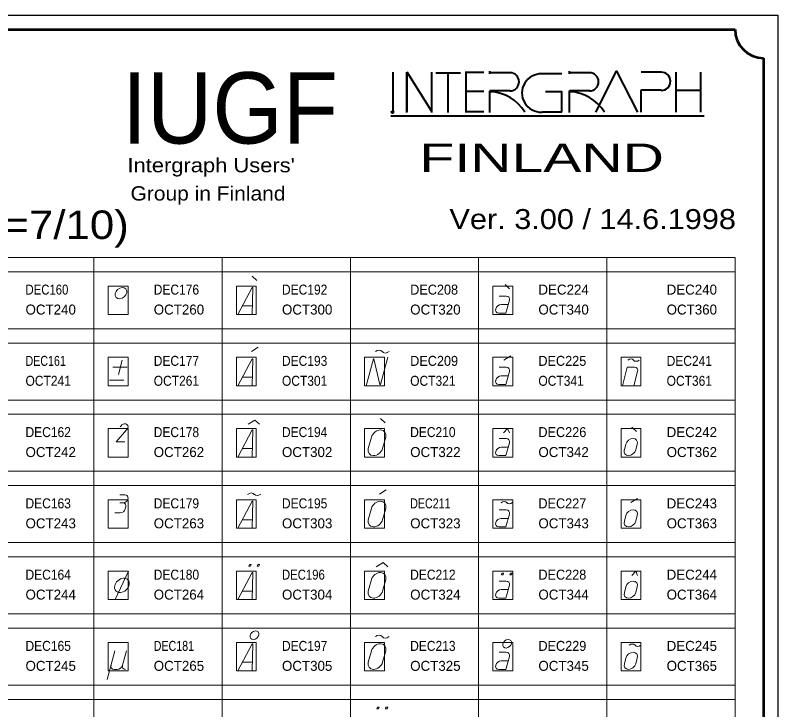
# Model space of a CAD drawing. Extents: x -200 to 7300, y -200 to 4800.
# Drawn here: x 4624 to 7300, y 2364 to 4800 of the extents above; entities that cross this region are included whole.
import ezdxf
from ezdxf.enums import TextEntityAlignment as Align

# ---------------------------------------------------------------- set-up
doc = ezdxf.new("R2010")
doc.units = 0
doc.header["$LTSCALE"] = 14
doc.header["$PDMODE"] = 32
doc.header["$PDSIZE"] = 7
for name, color, linetype, lineweight in [('1', 7, 'Continuous', 13), ('5', 7, 'Continuous', 40), ('6', 7, 'Continuous', 13), ('63', 7, 'Continuous', 13)]:
    doc.layers.add(name, color=color, linetype=linetype, lineweight=lineweight)
doc.layers.add('10', color=7, linetype='Continuous')
doc.layers.add('11', color=7, linetype='Continuous')

msp = doc.modelspace()

# ---------------------------------------------------------------- linework, layer by layer
at = {"layer": '1'}
for p, q in [((5472, 3870), (5456, 3885)), ((6359, 3840), (6343, 3855)), ((6322, 3815), (6347, 3815)), ((5421, 3780), (5457, 3780)), ((6329, 3785), (6354, 3785)), ((5453, 3620), (5477, 3635)), ((4986, 3540), (4999, 3590)), ((6339, 3590), (6363, 3605)), ((4967, 3565), (5017, 3565)), ((6322, 3565), (6347, 3565)), ((6329, 3535), (6354, 3535)), ((6808, 3550), (6795, 3500)), ((4955, 3520), (5005, 3520)), ((5421, 3530), (5457, 3530)), ((5922, 3370), (5906, 3385)), ((6804, 3340), (6788, 3355)), ((5874, 3320), (5863, 3280)), ((5924, 3320), (5913, 3280)), ((6322, 3315), (6347, 3315)), ((6767, 3295), (6762, 3275)), ((6807, 3295), (6802, 3275)), ((5421, 3280), (5457, 3280)), ((6329, 3285), (6354, 3285)), ((5902, 3120), (5926, 3135)), ((5009, 3117), (4991, 3117)), ((6784, 3090), (6808, 3105)), ((5002, 3089), (4991, 3089)), ((4992, 3054), (4974, 3054)), ((5012, 3075), (5010, 3068)), ((5874, 3070), (5863, 3030)), ((5924, 3070), (5913, 3030)), ((6322, 3065), (6347, 3065)), ((5421, 3030), (5457, 3030)), ((6329, 3035), (6354, 3035)), ((6767, 3045), (6762, 3025)), ((6807, 3045), (6802, 3025)), ((4975, 2750), (5022, 2850)), ((5874, 2820), (5863, 2780)), ((5924, 2820), (5913, 2780)), ((6322, 2815), (6347, 2815)), ((6329, 2785), (6354, 2785)), ((6767, 2795), (6762, 2775)), ((6807, 2795), (6802, 2775)), ((5421, 2780), (5457, 2780)), ((4974, 2570), (4947, 2470)), ((5014, 2570), (5000, 2520)), ((5874, 2570), (5863, 2530)), ((5924, 2570), (5913, 2530)), ((6322, 2565), (6347, 2565)), ((6767, 2545), (6762, 2525)), ((6807, 2545), (6802, 2525)), ((5421, 2530), (5457, 2530)), ((6329, 2535), (6354, 2535)), ((4971, 2505), (4981, 2505))]:
    msp.add_line(p, q, dxfattribs=at)
for points in [[(5405, 3750), (5455, 3845), (5458, 3845), (5456, 3750)], [(6358, 3800), (6346, 3755), (6321, 3755)], [(5405, 3500), (5455, 3595), (5458, 3595), (5456, 3500)], [(5855, 3500), (5881, 3595), (5883, 3595), (5904, 3505), (5906, 3505), (5932, 3600)], [(6755, 3500), (6772, 3565), (6797, 3565)], [(6358, 3550), (6346, 3505), (6321, 3505)], [(5481, 3365), (5465, 3380), (5441, 3365)], [(6358, 3335), (6352, 3350), (6338, 3335)], [(5009, 3304), (4978, 3304), (5015, 3345)], [(5405, 3250), (5455, 3345), (5458, 3345), (5456, 3250)], [(6358, 3300), (6346, 3255), (6321, 3255)], [(5405, 3000), (5455, 3095), (5458, 3095), (5456, 3000)], [(6358, 3050), (6346, 3005), (6321, 3005)], [(5931, 2865), (5915, 2880), (5891, 2865)], [(5405, 2750), (5455, 2845), (5458, 2845), (5456, 2750)], [(6808, 2835), (6802, 2850), (6788, 2835)], [(6358, 2800), (6346, 2755), (6321, 2755)], [(5405, 2500), (5455, 2595), (5458, 2595), (5456, 2500)], [(6358, 2550), (6346, 2505), (6321, 2505)]]:
    msp.add_lwpolyline(points, dxfattribs=at)
for points in [[(5444, 2867), (5450, 2867), (5452, 2873), (5446, 2873)], [(5473, 2867), (5479, 2867), (5481, 2873), (5475, 2873)], [(6330, 2837), (6336, 2837), (6338, 2843), (6332, 2843)], [(6360, 2837), (6366, 2837), (6368, 2843), (6362, 2843)], [(5893, 2367), (5899, 2367), (5901, 2373), (5895, 2373)], [(5923, 2367), (5929, 2367), (5931, 2373), (5925, 2373)]]:
    msp.add_lwpolyline(points, close=True, dxfattribs=at)
for centre, major_axis, ratio in [((4994.91, 3825), (-17.2, -15.05), 0.765566), ((4998.31, 2799.84), (-21.56, -18.83), 0.762607), ((5463.39, 2625), (-12.9, -11.29), 0.765566), ((6350.36, 2595), (-12.9, -11.29), 0.765566)]:
    msp.add_ellipse(centre, major_axis=major_axis, ratio=ratio, dxfattribs=at)
for centre, major_axis, start_param, end_param in [((6343, 3800), (-12.9, -11.29), 2.2896327, 3.860429), ((6325.19, 3770), (-12.9, -11.29), 3.860429, 7.0020216), ((5896.78, 3608), (-14.6, -12.77), 3.0750308, 4.6457939), ((5927.21, 3632), (-14.6, -12.77), 6.2166235, 7.7873867), ((6781.29, 3580), (-12.16, -10.64), 3.0750308, 4.6458271), ((6806.65, 3600), (-12.16, -10.64), 6.2166235, 7.7874198), ((6343, 3550), (-12.9, -11.29), 2.2896327, 3.860429), ((6793, 3550), (-12.9, -11.29), 2.2896327, 3.860429), ((6325.21, 3520), (-12.9, -11.29), 3.860429, 7.0020216), ((5005.28, 3352.61), (-12.04, -10.54), 1.7153279, 5.1862467), ((5899, 3320), (-21.5, -18.81), 2.2896326, 5.4312252), ((6343, 3300), (-12.9, -11.29), 2.2896327, 3.860429), ((6786.93, 3295), (-17.2, -15.05), 2.2896326, 5.4312252), ((5888, 3280), (21.5, 18.81), 2.2896328, 5.4312254), ((6325.22, 3270), (-12.9, -11.29), 3.860429, 7.0020216), ((6781.57, 3275), (17.2, 15.05), 2.2896328, 5.4312254), ((5005.47, 3102.98), (-12.06, -10.55), 0.646299, 3.8615683), ((5447.8, 3107), (-14.6, -12.77), 3.0750308, 4.6457939), ((5477.23, 3132), (-14.6, -12.77), 6.2166235, 7.7873867), ((4997.96, 3075), (-12.04, -10.54), 2.2896326, 3.8604289), ((5899, 3070), (-21.5, -18.81), 2.2896326, 5.4312252), ((6336.31, 3080), (-12.16, -10.64), 3.0750308, 4.6458271), ((6361.67, 3100), (-12.16, -10.64), 6.2166235, 7.7874198), ((4996.08, 3068), (12.04, 10.54), 3.860429, 5.4312252), ((6343, 3050), (-12.9, -11.29), 2.2896327, 3.860429), ((6786.94, 3045), (-17.2, -15.05), 2.2896326, 5.4312252), ((5888, 3030), (21.5, 18.81), 2.2896328, 5.4312254), ((6325.24, 3020), (-12.9, -11.29), 3.860429, 7.0020216), ((6781.58, 3025), (17.2, 15.05), 2.2896328, 5.4312254), ((5899, 2820), (-21.5, -18.81), 2.2896326, 5.4312252), ((6343, 2800), (-12.9, -11.29), 2.2896327, 3.860429), ((6786.96, 2795), (-17.2, -15.05), 2.2896326, 5.4312252), ((6325.25, 2770), (-12.9, -11.29), 3.860429, 7.0020216), ((5888, 2780), (21.5, 18.81), 2.2896328, 5.4312254), ((6781.6, 2775), (17.2, 15.05), 2.2896328, 5.4312254), ((5896.84, 2608), (-14.6, -12.77), 3.0750308, 4.6457939), ((5927.27, 2632), (-14.6, -12.77), 6.2166235, 7.7873867), ((5899, 2570), (-21.5, -18.81), 2.2896326, 5.4312252), ((6786.35, 2580), (-12.16, -10.64), 3.0750308, 4.6458271), ((6811.71, 2600), (-12.16, -10.64), 6.2166235, 7.7874198), ((6343, 2550), (-12.9, -11.29), 2.2896327, 3.860429), ((6786.97, 2545), (-17.2, -15.05), 2.2896326, 5.4312252), ((4975.25, 2520), (12.9, 11.29), 2.2896327, 3.860429), ((4985.25, 2520), (-12.9, -11.29), 0.7188363, 2.2896326), ((5015.25, 2520), (12.9, 11.29), 2.2896328, 3.860429), ((5888, 2530), (21.5, 18.81), 2.2896328, 5.4312254), ((6325.27, 2520), (-12.9, -11.29), 3.860429, 7.0020216), ((6781.61, 2525), (17.2, 15.05), 2.2896328, 5.4312254)]:
    msp.add_ellipse(centre, major_axis=major_axis, ratio=0.765566, start_param=start_param, end_param=end_param, dxfattribs=at)
at = {"layer": '5', "lineweight": 53}
for p, q in [((-50, 4750), (7150, 4750)), ((7250, 4650), (7250, -50))]:
    msp.add_line(p, q, dxfattribs=at)
at = {"layer": '5'}
for p, q in [((6290, 4595), (6290, 4604)), ((6569, 4595), (6569, 4604)), ((5950, 4459), (5950, 4600)), ((5998, 4459), (5998, 4600)), ((5999, 4462), (5999, 4600)), ((6086, 4462), (5999, 4600)), ((6086, 4459), (6086, 4600)), ((6100, 4598), (6187, 4598)), ((6143, 4459), (6143, 4600)), ((6203, 4600), (6269, 4600)), ((6205, 4600), (6205, 4460)), ((6361, 4598), (6290, 4598)), ((6542, 4595), (6473, 4595)), ((6640, 4598), (6569, 4598)), ((6892, 4600), (6821, 4600)), ((6943, 4460), (6943, 4600)), ((7030, 4460), (7030, 4600)), ((6203, 4534), (6269, 4534)), ((6361, 4535), (6290, 4535)), ((6290, 4459), (6290, 4535)), ((6640, 4535), (6569, 4535)), ((6569, 4459), (6569, 4535)), ((6821, 4460), (6821, 4538)), ((6892, 4537), (6821, 4537)), ((6944, 4537), (7027, 4537)), ((5942, 4447), (7042, 4447)), ((6203, 4462), (6269, 4462)), ((6542, 4460), (6473, 4460))]:
    msp.add_line(p, q, dxfattribs=at)
at = {"layer": '5', "lineweight": 25}
msp.add_lwpolyline([(-200, -200), (-200, 4800), (7300, 4800), (7300, -200)], close=True, dxfattribs=at)
at = {"layer": '5'}
for points in [[(6662, 4460), (6734, 4604), (6808, 4460)], [(6662, 4460), (6734, 4604), (6808, 4460)], [(6542, 4460), (6542, 4531), (6485, 4531)]]:
    msp.add_lwpolyline(points, dxfattribs=at)
at = {"layer": '5', "lineweight": 53}
msp.add_arc((7250.23, 4750.23), 100.23, 180.13245, 269.86755, dxfattribs=at)
at = {"layer": '5'}
for centre, radius, start, end in [((6359.95, 4566.47), 32.08, 270, 89.99999), ((6469.54, 4527.31), 67.13, 87.55561, 272.44438), ((6639.2, 4566.47), 32.08, 270, 89.99999), ((6891.34, 4568.25), 32.08, 270, 89.99999), ((6282.86, 4378.09), 153.83, 32.38854, 87.01955), ((6562.1, 4378.09), 153.83, 32.38854, 87.01955)]:
    msp.add_arc(centre, radius, start, end, dxfattribs=at)
msp.add_point((5948, 4460), dxfattribs=at)
at = {"layer": '6'}
for p, q in [((-50, 3950), (7150, 3950)), ((4900, 3950), (4900, -50)), ((5350, 3950), (5350, -50)), ((5800, 3950), (5800, -50)), ((6250, 3950), (6250, -50)), ((6700, 3950), (6700, -50)), ((7150, 3950), (7150, -50)), ((-50, 3900), (7150, 3900)), ((-50, 3700), (7150, 3700)), ((-50, 3650), (7150, 3650)), ((-50, 3450), (7150, 3450)), ((-50, 3400), (7150, 3400)), ((-50, 3200), (7150, 3200)), ((-50, 3150), (7150, 3150)), ((-50, 2950), (7150, 2950)), ((-50, 2900), (7150, 2900)), ((-50, 2700), (7150, 2700)), ((-50, 2650), (7150, 2650)), ((-50, 2450), (7150, 2450)), ((-50, 2400), (7150, 2400))]:
    msp.add_line(p, q, dxfattribs=at)
at = {"layer": '63'}
for points in [[(4950, 3750), (5020, 3750), (5020, 3850), (4950, 3850)], [(5400, 3750), (5470, 3750), (5470, 3850), (5400, 3850)], [(6300, 3750), (6370, 3750), (6370, 3850), (6300, 3850)], [(4950, 3500), (5020, 3500), (5020, 3600), (4950, 3600)], [(5400, 3500), (5470, 3500), (5470, 3600), (5400, 3600)], [(5850, 3500), (5920, 3500), (5920, 3600), (5850, 3600)], [(6300, 3500), (6370, 3500), (6370, 3600), (6300, 3600)], [(6750, 3500), (6820, 3500), (6820, 3600), (6750, 3600)], [(4950, 3250), (5020, 3250), (5020, 3350), (4950, 3350)], [(5400, 3250), (5470, 3250), (5470, 3350), (5400, 3350)], [(5850, 3250), (5920, 3250), (5920, 3350), (5850, 3350)], [(6300, 3250), (6370, 3250), (6370, 3350), (6300, 3350)], [(6750, 3250), (6820, 3250), (6820, 3350), (6750, 3350)], [(4950, 3000), (5020, 3000), (5020, 3100), (4950, 3100)], [(5400, 3000), (5470, 3000), (5470, 3100), (5400, 3100)], [(5850, 3000), (5920, 3000), (5920, 3100), (5850, 3100)], [(6300, 3000), (6370, 3000), (6370, 3100), (6300, 3100)], [(6750, 3000), (6820, 3000), (6820, 3100), (6750, 3100)], [(4950, 2750), (5020, 2750), (5020, 2850), (4950, 2850)], [(5400, 2750), (5470, 2750), (5470, 2850), (5400, 2850)], [(5850, 2750), (5920, 2750), (5920, 2850), (5850, 2850)], [(6300, 2750), (6370, 2750), (6370, 2850), (6300, 2850)], [(6750, 2750), (6820, 2750), (6820, 2850), (6750, 2850)], [(4950, 2500), (5020, 2500), (5020, 2600), (4950, 2600)], [(5400, 2500), (5470, 2500), (5470, 2600), (5400, 2600)], [(5850, 2500), (5920, 2500), (5920, 2600), (5850, 2600)], [(6300, 2500), (6370, 2500), (6370, 2600), (6300, 2600)], [(6750, 2500), (6820, 2500), (6820, 2600), (6750, 2600)]]:
    msp.add_lwpolyline(points, close=True, dxfattribs=at)

# ---------------------------------------------------------------- texts
at = {"layer": '10'}
for s, width, p in [('DEC160', 0.85, (4660, 3820)), ('DEC176', 0.9, (5110, 3820)), ('DEC192', 0.9, (5560, 3820)), ('DEC208', 0.95, (6010, 3820)), ('DEC161', 0.8, (4660, 3570)), ('DEC177', 0.9, (5110, 3570)), ('DEC193', 0.9, (5560, 3570)), ('DEC209', 0.95, (6010, 3570)), ('DEC225', 0.95, (6460, 3570)), ('DEC241', 0.9, (6910, 3570)), ('DEC162', 0.9, (4660, 3320)), ('DEC178', 0.9, (5110, 3320)), ('DEC194', 0.9, (5560, 3320)), ('DEC210', 0.9, (6010, 3320)), ('DEC226', 0.95, (6460, 3320)), ('DEC163', 0.9, (4660, 3070)), ('DEC179', 0.9, (5110, 3070)), ('DEC195', 0.9, (5560, 3070)), ('DEC211', 0.8, (6010, 3070)), ('DEC227', 0.95, (6460, 3070)), ('DEC164', 0.9, (4660, 2820)), ('DEC180', 0.9, (5110, 2820)), ('DEC196', 0.85, (5560, 2820)), ('DEC212', 0.9, (6010, 2820)), ('DEC228', 0.95, (6460, 2820)), ('DEC165', 0.9, (4660, 2570)), ('DEC181', 0.8, (5110, 2570)), ('DEC197', 0.9, (5560, 2570)), ('DEC213', 0.9, (6010, 2570)), ('DEC229', 0.95, (6460, 2570))]:
    msp.add_text(s, height=35, dxfattribs=dict(at, width=width)).set_placement(p)
for s, p in [('DEC224', (6460, 3820)), ('DEC240', (6910, 3820)), ('DEC242', (6910, 3320)), ('DEC243', (6910, 3070)), ('DEC244', (6910, 2820)), ('DEC245', (6910, 2570))]:
    msp.add_text(s, height=35, dxfattribs=at).set_placement(p)
at = {"layer": '11'}
for s, p in [('OCT240', (4660, 3750)), ('OCT260', (5110, 3750)), ('OCT300', (5560, 3750)), ('OCT320', (6010, 3750)), ('OCT340', (6460, 3750)), ('OCT360', (6910, 3750)), ('OCT242', (4660, 3250)), ('OCT262', (5110, 3250)), ('OCT302', (5560, 3250)), ('OCT322', (6010, 3250)), ('OCT342', (6460, 3250)), ('OCT362', (6910, 3250)), ('OCT243', (4660, 3000)), ('OCT263', (5110, 3000)), ('OCT303', (5560, 3000)), ('OCT323', (6010, 3000)), ('OCT343', (6460, 3000)), ('OCT363', (6910, 3000)), ('OCT244', (4660, 2750)), ('OCT264', (5110, 2750)), ('OCT304', (5560, 2750)), ('OCT324', (6010, 2750)), ('OCT344', (6460, 2750)), ('OCT364', (6910, 2750)), ('OCT245', (4660, 2500)), ('OCT265', (5110, 2500)), ('OCT305', (5560, 2500)), ('OCT325', (6010, 2500)), ('OCT345', (6460, 2500)), ('OCT365', (6910, 2500))]:
    msp.add_text(s, height=35, dxfattribs=at).set_placement(p)
at = {"layer": '11', "width": 0.9}
for s, p in [('OCT241', (4660, 3500)), ('OCT261', (5110, 3500)), ('OCT301', (5560, 3500)), ('OCT321', (6010, 3500)), ('OCT341', (6460, 3500)), ('OCT361', (6910, 3500))]:
    msp.add_text(s, height=35, dxfattribs=at).set_placement(p)
at = {"layer": '5'}
for s, height, width, p in [('IUGF', 250, 0.95, (5377.5, 4350)), ('FINLAND', 100, 1.5, (6471.5, 4250)), ("Intergraph Users'", 50, 1.15, (5311.5, 4249)), ('Group in Finland', 50, 1.1, (5300.5, 4150)), ('ISO 3098 Lettering B Inclined (15°) Equal (w/h=7/10)', 100, 1.15, (3224.5, 4015))]:
    msp.add_text(s, height=height, dxfattribs=dict(at, width=width)).set_placement(p, align=Align.CENTER)
at = {"layer": '5', "width": 1.15}
msp.add_text('Ver. 3.00 / 14.6.1998', height=70, dxfattribs=at).set_placement((7153.3, 4050), align=Align.RIGHT)

doc.saveas('drawing.dxf')
